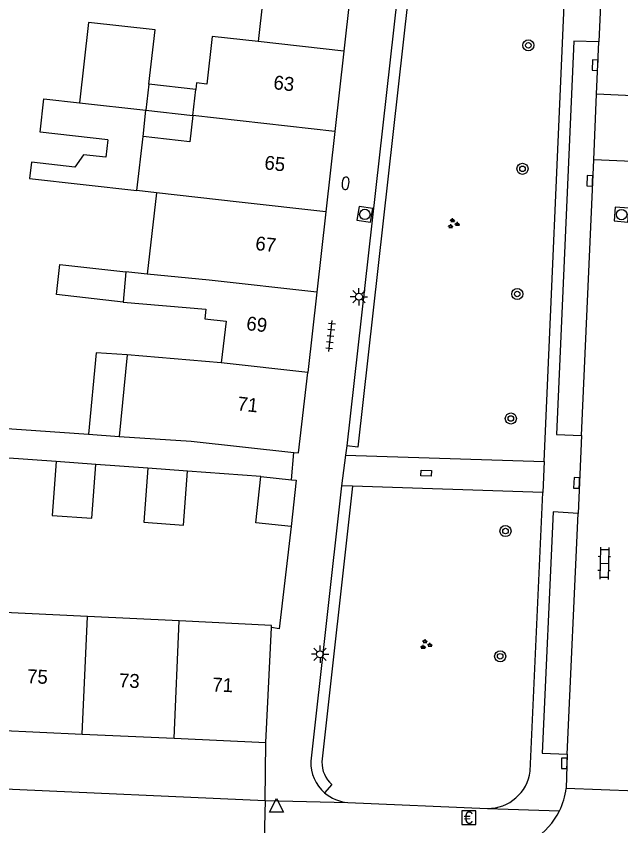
# Model space of a CAD drawing. Extents: x 132994 to 136000, y 393499 to 395512.
# Drawn here: x 133113.3 to 133156.9, y 395185.2 to 395243.6 of the extents above; entities that cross this region are included whole.
import ezdxf

# ---------------------------------------------------------------- set-up
doc = ezdxf.new("R2010")
doc.units = 0
for name, color, linetype in [('gg-afsc-erfafscheiding', 7, 'Continuous'), ('gg-afsc-hekwerk', 7, 'Continuous'), ('gg-afsc-muur', 7, 'Continuous'), ('gg-anno-huisnummerreeks BGT', 7, 'Continuous'), ('gg-bbg-bijgebouw', 7, 'Continuous'), ('gg-bbg-gedigitaliseerde bebouwing', 7, 'Continuous'), ('gg-bbg-gedigitaliseerde bijgebouw', 7, 'Continuous'), ('gg-bbg-hoofdgebouw', 7, 'Continuous'), ('gg-bbg-luifel en loopbrug', 7, 'Continuous'), ('gg-bbg-tussenscheiding', 7, 'Continuous'), ('gg-knt-verharding', 7, 'Continuous'), ('gg-knt-verharding nz', 7, 'Continuous'), ('gt-grn-groengrens', 7, 'Continuous'), ('gt-grn-weggrens', 7, 'Continuous'), ('gt-symb-betaalautomaat', 7, 'Continuous'), ('gt-symb-boom', 7, 'Continuous'), ('gt-symb-brandkraan', 7, 'Continuous'), ('gt-symb-groenvak', 7, 'Continuous'), ('gt-symb-klinker verharding', 7, 'Continuous'), ('gt-symb-kolk', 7, 'Continuous'), ('gt-symb-kolk center center', 7, 'Continuous'), ('gt-symb-lichtmast', 7, 'Continuous'), ('gt-symb-rioolschacht', 7, 'Continuous'), ('gt-symb-tegel verharding', 7, 'Continuous'), ('gt-symb-waterafsluiter', 7, 'Continuous')]:
    doc.layers.add(name, color=color, linetype=linetype)

# ---------------------------------------------------------------- blocks, each defined once
blk = doc.blocks.new('gt0-KOLK')
at = {"layer": 'gt-symb-kolk'}
blk.add_lwpolyline([(0, 0), (0.375, 0), (0.375, 0.4), (-0.375, 0.4), (-0.375, 0), (0, 0)], dxfattribs=at)
blk = doc.blocks.new('gt0-BOOM')
at = {"layer": 'gt-symb-boom'}
for radius in [0.4, 0.2]:
    blk.add_circle((0, 0), radius, dxfattribs=at)
blk = doc.blocks.new('gt0-RS')
at = {"layer": 'gt-symb-rioolschacht'}
blk.add_lwpolyline([(-0.5, -0.5), (0.5, -0.5), (0.5, 0.5), (-0.5, 0.5)], close=True, dxfattribs=at)
blk.add_circle((0, 0), 0.375, dxfattribs=at)
blk = doc.blocks.new('gt0-KL1')
at = {"layer": 'gt-symb-klinker verharding'}
for p, q in [((-1.15, 0.3), (1.15, 0.3)), ((-1, -0.3), (-1, 0.3)), ((-0.5, 0.3), (-0.5, 0.45)), ((0, -0.3), (0, 0.3)), ((0.5, 0.3), (0.5, 0.45)), ((1, -0.3), (1, 0.3)), ((-1.15, -0.3), (1.15, -0.3)), ((-0.5, -0.45), (-0.5, -0.3)), ((0.5, -0.45), (0.5, -0.3))]:
    blk.add_line(p, q, dxfattribs=at)
blk = doc.blocks.new('gt0-TEG1')
at = {"layer": 'gt-symb-tegel verharding'}
for p, q in [((-1.125, 0), (1.125, 0)), ((-0.9, -0.25), (-0.9, 0.25)), ((-0.45, -0.25), (-0.45, 0.25)), ((0, -0.25), (0, 0.25)), ((0.45, -0.25), (0.45, 0.25)), ((0.9, -0.25), (0.9, 0.25))]:
    blk.add_line(p, q, dxfattribs=at)
blk = doc.blocks.new('gt0-BR')
at = {"layer": 'gt-symb-brandkraan'}
for centre, radius, start, end in [((-0.244, 0), 0.206, 107.56694, 252.43307), ((0.599, -2.664), 3, 106.89205, 107.56694), ((0, -0.691), 0.938, 73.10799, 106.89205), ((-0.599, -2.664), 3, 72.43309, 73.10799), ((0.244, 0), 0.206, 287.56695, 72.43309), ((0.599, 2.664), 3, 252.43307, 253.10797), ((0, 0.691), 0.938, 253.10797, 286.89206), ((-0.599, 2.664), 3, 286.89206, 287.56695)]:
    blk.add_arc(centre, radius, start, end, dxfattribs=at)
blk = doc.blocks.new('gt0-LMAST')
at = {"layer": 'gt-symb-lichtmast'}
for p, q in [((-0.005, 0.246), (-0.005, 0.621)), ((-0.182, 0.173), (-0.447, 0.438)), ((0.172, 0.173), (0.437, 0.438)), ((-0.255, -0.004), (-0.63, -0.004)), ((-0.182, -0.181), (-0.447, -0.446)), ((-0.005, -0.254), (-0.005, -0.629)), ((0.437, -0.446), (0.172, -0.181)), ((0.245, -0.004), (0.62, -0.004))]:
    blk.add_line(p, q, dxfattribs=at)
blk.add_circle((-0.005, -0.004), 0.25, dxfattribs=at)
blk = doc.blocks.new('gt0-GRVAK')
at = {"layer": 'gt-symb-groenvak'}
for p, q in [((-0.11, 0.189), (-0.228, 0.24)), ((-0.182, 0.153), (0.088, 0.153)), ((-0.091, 0.211), (-0.156, 0.322)), ((-0.047, 0.214), (-0.047, 0.393)), ((-0.004, 0.211), (0.061, 0.322)), ((0.015, 0.189), (0.133, 0.24)), ((0.262, -0.052), (0.197, 0.059)), ((0.305, -0.049), (0.305, 0.13)), ((0.349, -0.052), (0.414, 0.059)), ((-0.245, -0.228), (-0.363, -0.177)), ((-0.318, -0.264), (-0.047, -0.264)), ((-0.226, -0.206), (-0.291, -0.095)), ((-0.183, -0.203), (-0.183, -0.024)), ((-0.139, -0.206), (-0.074, -0.095)), ((-0.12, -0.228), (-0.002, -0.177)), ((0.243, -0.074), (0.125, -0.023)), ((0.17, -0.11), (0.441, -0.11)), ((0.368, -0.074), (0.486, -0.023))]:
    blk.add_line(p, q, dxfattribs=at)
blk = doc.blocks.new('gt0-KOLKCC')
at = {"layer": 'gt-symb-kolk center center'}
blk.add_lwpolyline([(-0.375, 0.2), (0.375, 0.2), (0.375, -0.2), (-0.375, -0.2)], close=True, dxfattribs=at)
blk = doc.blocks.new('gt0-BA')
at = {"layer": 'gt-symb-betaalautomaat'}
blk.add_lwpolyline([(-0.498, -0.507), (0.502, -0.507), (0.502, 0.493), (-0.498, 0.493)], close=True, dxfattribs=at)
blk.add_text('€', height=0.9, dxfattribs=at).set_placement((-0.357, -0.457))
blk = doc.blocks.new('gt0-WAFSL')
at = {"layer": 'gt-symb-waterafsluiter'}
for p, q in [((-0.5, -0.333), (0, 0.667)), ((0, 0.667), (0.5, -0.333)), ((0.5, -0.333), (-0.5, -0.333))]:
    blk.add_line(p, q, dxfattribs=at)

msp = doc.modelspace()

# ---------------------------------------------------------------- linework, layer by layer
at = {"layer": 'gg-afsc-erfafscheiding'}
for p, q in [((133111.363, 395213.934), (133118.513, 395213.442)), ((133116.181, 395211.472), (133112.421, 395211.747)), ((133122.797, 395210.99), (133119.038, 395211.264)), ((133130.95, 395210.395), (133125.654, 395210.782))]:
    msp.add_line(p, q, dxfattribs=at)
at = {"layer": 'gg-afsc-hekwerk'}
msp.add_line((133133.155, 395210.155), (133133.322, 395212.128), dxfattribs=at)
at = {"layer": 'gg-afsc-muur'}
msp.add_lwpolyline([(133133.125, 395206.788), (133132.27, 395199.41), (133131.713, 395199.5)], dxfattribs=at)
at = {"layer": 'gg-bbg-bijgebouw'}
msp.add_line((133130.95, 395210.395), (133133.155, 395210.155), dxfattribs=at)
for points in [[(133133.125, 395206.788), (133130.59, 395207.064), (133130.95, 395210.395)], [(133133.155, 395210.155), (133133.488, 395210.119), (133133.125, 395206.788)]]:
    msp.add_lwpolyline(points, dxfattribs=at)
at = {"layer": 'gg-bbg-gedigitaliseerde bebouwing'}
for p, q in [((133122.008, 395231.009), (133122.449, 395234.921)), ((133123.413, 395230.85), (133122.008, 395231.009)), ((133123.413, 395230.85), (133122.755, 395224.991)), ((133122.755, 395224.991), (133121.197, 395225.144)), ((133121.299, 395219.161), (133120.737, 395213.289)), ((133128.083, 395218.587), (133121.299, 395219.161)), ((133118.436, 395200.296), (133111.812, 395200.618)), ((133125.06, 395199.974), (133118.436, 395200.296)), ((133131.72, 395199.65), (133125.06, 395199.974))]:
    msp.add_line(p, q, dxfattribs=at)
for points in [[(133129.81, 395247.737), (133129.498, 395244.961), (133131.088, 395244.783), (133130.757, 395241.761)], [(133130.757, 395241.761), (133127.432, 395242.135), (133127.044, 395238.696), (133126.311, 395238.788), (133126.257, 395238.305)], [(133121.016, 395222.971), (133126.974, 395222.473), (133126.895, 395221.768), (133128.433, 395221.595), (133128.083, 395218.587)]]:
    msp.add_lwpolyline(points, dxfattribs=at)
at = {"layer": 'gg-bbg-gedigitaliseerde bijgebouw'}
for p, q in [((133122.872, 395238.685), (133122.66, 395236.803)), ((133126.257, 395238.305), (133122.872, 395238.685)), ((133122.449, 395234.921), (133122.66, 395236.803)), ((133119.038, 395211.264), (133116.181, 395211.472)), ((133125.654, 395210.782), (133122.797, 395210.99))]:
    msp.add_line(p, q, dxfattribs=at)
for points in [[(133121.016, 395222.971), (133116.213, 395223.51), (133116.456, 395225.676), (133121.197, 395225.144)], [(133116.181, 395211.472), (133115.898, 395207.586), (133118.755, 395207.378), (133119.038, 395211.264)], [(133122.797, 395210.99), (133122.514, 395207.104), (133125.37, 395206.896), (133125.654, 395210.782)]]:
    msp.add_lwpolyline(points, dxfattribs=at)
at = {"layer": 'gg-bbg-hoofdgebouw'}
for p, q in [((133137.581, 395246.862), (133136.929, 395241.067)), ((133136.929, 395241.067), (133136.278, 395235.272)), ((133136.278, 395235.272), (133135.626, 395229.476)), ((133135.626, 395229.476), (133134.973, 395223.681)), ((133134.973, 395223.681), (133134.322, 395217.885)), ((133133.67, 395212.09), (133134.322, 395217.885)), ((133133.322, 395212.128), (133133.67, 395212.09)), ((133131.713, 395199.5), (133131.72, 395199.65)), ((133131.31, 395191.22), (133131.713, 395199.5)), ((133111.431, 395192.113), (133118.056, 395191.816)), ((133118.056, 395191.816), (133124.681, 395191.518)), ((133124.681, 395191.518), (133131.31, 395191.22))]:
    msp.add_line(p, q, dxfattribs=at)
msp.add_lwpolyline([(133120.737, 395213.289), (133125.924, 395212.947), (133133.322, 395212.128)], dxfattribs=at)
at = {"layer": 'gg-bbg-luifel en loopbrug'}
for p, q in [((133117.855, 395237.342), (133122.66, 395236.803)), ((133118.513, 395213.442), (133120.737, 395213.289))]:
    msp.add_line(p, q, dxfattribs=at)
for points in [[(133122.872, 395238.685), (133123.311, 395242.597), (133118.506, 395243.137), (133117.855, 395237.342)], [(133119.905, 395234.684), (133115.036, 395235.231), (133115.305, 395237.629), (133117.855, 395237.342)], [(133119.905, 395234.684), (133119.763, 395233.42), (133118.16, 395233.602), (133117.533, 395232.704), (133114.392, 395233.055), (133114.26, 395231.879), (133122.008, 395231.009)], [(133121.299, 395219.161), (133119.074, 395219.305), (133118.513, 395213.442)]]:
    msp.add_lwpolyline(points, dxfattribs=at)
at = {"layer": 'gg-bbg-tussenscheiding'}
for p, q in [((133136.929, 395241.067), (133130.757, 395241.761)), ((133126.046, 395236.423), (133126.257, 395238.305)), ((133122.66, 395236.803), (133126.046, 395236.423)), ((133136.278, 395235.272), (133126.046, 395236.423)), ((133121.197, 395225.144), (133121.016, 395222.971)), ((133134.322, 395217.885), (133128.083, 395218.587)), ((133118.056, 395191.816), (133118.436, 395200.296)), ((133124.681, 395191.518), (133125.06, 395199.974))]:
    msp.add_line(p, q, dxfattribs=at)
for points in [[(133126.046, 395236.423), (133125.834, 395234.54), (133122.449, 395234.921)], [(133135.626, 395229.476), (133129.388, 395230.178), (133123.413, 395230.85)], [(133134.973, 395223.681), (133127.209, 395224.554), (133122.755, 395224.991)]]:
    msp.add_lwpolyline(points, dxfattribs=at)
at = {"layer": 'gg-knt-verharding'}
for p, q in [((133155.706, 395250.62), (133155.31, 395241.748)), ((133140.853, 395245.677), (133137.136, 395212.61)), ((133151.378, 395211.47), (133152.854, 395245.153)), ((133154.947, 395233.221), (133155.16, 395237.957)), ((133160.278, 395237.723), (133155.16, 395237.957)), ((133160.057, 395233.02), (133154.947, 395233.221)), ((133154.06, 395213.339), (133153.832, 395207.736)), ((133137.136, 395212.61), (133137.061, 395211.939)), ((133137.061, 395211.939), (133151.378, 395211.47)), ((133136.758, 395209.731), (133134.549, 395189.863)), ((133137.56, 395209.704), (133136.758, 395209.731)), ((133151.282, 395209.236), (133137.56, 395209.704)), ((133150.379, 395189.136), (133151.282, 395209.236)), ((133131.258, 395187.03), (133131.31, 395191.22)), ((133153.038, 395190.36), (133152.96, 395187.898)), ((133071.527, 395189.735), (133131.258, 395187.03)), ((133158.011, 395187.703), (133152.96, 395187.898)), ((133137.218, 395186.888), (133147.293, 395186.449))]:
    msp.add_line(p, q, dxfattribs=at)
for points in [[(133155.31, 395241.748), (133153.523, 395241.797), (133152.269, 395213.426), (133154.06, 395213.339)], [(133153.832, 395207.736), (133152.019, 395207.841), (133151.229, 395190.444), (133153.038, 395190.36)]]:
    msp.add_lwpolyline(points, dxfattribs=at)
for centre, radius, start, end in [((133137.426, 395189.759), 2.879, 177.93748, 229.17895), ((133147.285, 395189.573), 3.124, 270.14077, 351.95183), ((133147.968, 395188.498), 5.028, 333.97013, 353.14265), ((133137.426, 395189.759), 2.879, 229.17166, 265.85134), ((133147.952, 395188.5), 5.043, 270.39869, 334.03465)]:
    msp.add_arc(centre, radius, start, end, dxfattribs=at)
at = {"layer": 'gg-knt-verharding nz'}
for p, q in [((133155.16, 395237.957), (133155.31, 395241.748)), ((133154.06, 395213.339), (133154.947, 395233.221)), ((133153.038, 395190.36), (133153.832, 395207.736))]:
    msp.add_line(p, q, dxfattribs=at)
at = {"layer": 'gt-grn-groengrens'}
for p, q in [((133141.654, 395245.642), (133137.931, 395212.519)), ((133137.931, 395212.519), (133137.136, 395212.61)), ((133137.56, 395209.704), (133135.348, 395189.807)), ((133136.067, 395188.186), (133135.544, 395187.581))]:
    msp.add_line(p, q, dxfattribs=at)
msp.add_arc((133137.426, 395189.759), 2.079, 178.67541, 229.16427, dxfattribs=at)
at = {"layer": 'gt-grn-weggrens'}
for p, q in [((133137.061, 395211.939), (133136.758, 395209.731)), ((133151.378, 395211.47), (133151.282, 395209.236)), ((133131.258, 395187.03), (133131.193, 395184.175)), ((133131.258, 395187.03), (133137.218, 395186.888)), ((133147.293, 395186.449), (133152.486, 395186.292))]:
    msp.add_line(p, q, dxfattribs=at)

# ---------------------------------------------------------------- block references
at = {"layer": 'gt-symb-betaalautomaat'}
msp.add_blockref('gt0-BA', (133145.936, 395185.798), dxfattribs=at)
at = {"layer": 'gt-symb-boom'}
for p in [(133150.238, 395241.491), (133149.812, 395232.585), (133149.434, 395223.555), (133148.974, 395214.575), (133148.585, 395206.457), (133148.207, 395197.43)]:
    msp.add_blockref('gt0-BOOM', p, dxfattribs=at)
at = {"layer": 'gt-symb-brandkraan', "rotation": -96.20097099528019}
msp.add_blockref('gt0-BR', (133137.055, 395231.544), dxfattribs=at)
at = {"layer": 'gt-symb-groenvak'}
for p in [(133144.82, 395228.622), (133142.833, 395198.275)]:
    msp.add_blockref('gt0-GRVAK', p, dxfattribs=at)
at = {"layer": 'gt-symb-klinker verharding', "rotation": -91.2030345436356}
msp.add_blockref('gt0-KL1', (133155.707, 395204.13), dxfattribs=at)
at = {"layer": 'gt-symb-kolk'}
for p, rotation in [((133155.247, 395240.048), 87.59258615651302), ((133154.873, 395231.712), 87.47809205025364), ((133153.917, 395209.919), 87.59258615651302), ((133153.025, 395189.705), 88.85423716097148)]:
    msp.add_blockref('gt0-KOLK', p, dxfattribs=dict(at, rotation=rotation))
at = {"layer": 'gt-symb-kolk center center', "rotation": -2.0638197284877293}
msp.add_blockref('gt0-KOLKCC', (133142.871, 395210.634), dxfattribs=at)
at = {"layer": 'gt-symb-lichtmast'}
for p in [(133138.021, 395223.365), (133135.217, 395197.581)]:
    msp.add_blockref('gt0-LMAST', p, dxfattribs=at)
at = {"layer": 'gt-symb-rioolschacht'}
for p, rotation in [((133138.444, 395229.298), -98.91603673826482), ((133156.959, 395229.281), -94.75888567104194)]:
    msp.add_blockref('gt0-RS', p, dxfattribs=dict(at, rotation=rotation))
at = {"layer": 'gt-symb-tegel verharding', "rotation": 83.74206607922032}
msp.add_blockref('gt0-TEG1', (133135.971, 395220.518), dxfattribs=at)
at = {"layer": 'gt-symb-waterafsluiter'}
msp.add_blockref('gt0-WAFSL', (133132.068, 395186.515), dxfattribs=at)

# ---------------------------------------------------------------- texts
at = {"layer": 'gg-anno-huisnummerreeks BGT'}
for s, rotation, p in [('63', 353.6, (133131.815, 395238.335)), ('65', 353.6, (133131.165, 395232.554)), ('67', 353.6, (133130.51, 395226.734)), ('69', 353.6, (133129.86, 395220.957)), ('71', 353.6, (133129.21, 395215.176)), ('75', 357.4, (133114.07, 395195.499)), ('73', 357.4, (133120.695, 395195.201)), ('71', 357.4, (133127.429, 395194.899))]:
    msp.add_text(s, height=1, rotation=rotation, dxfattribs=at).set_placement(p)

doc.saveas('drawing.dxf')
